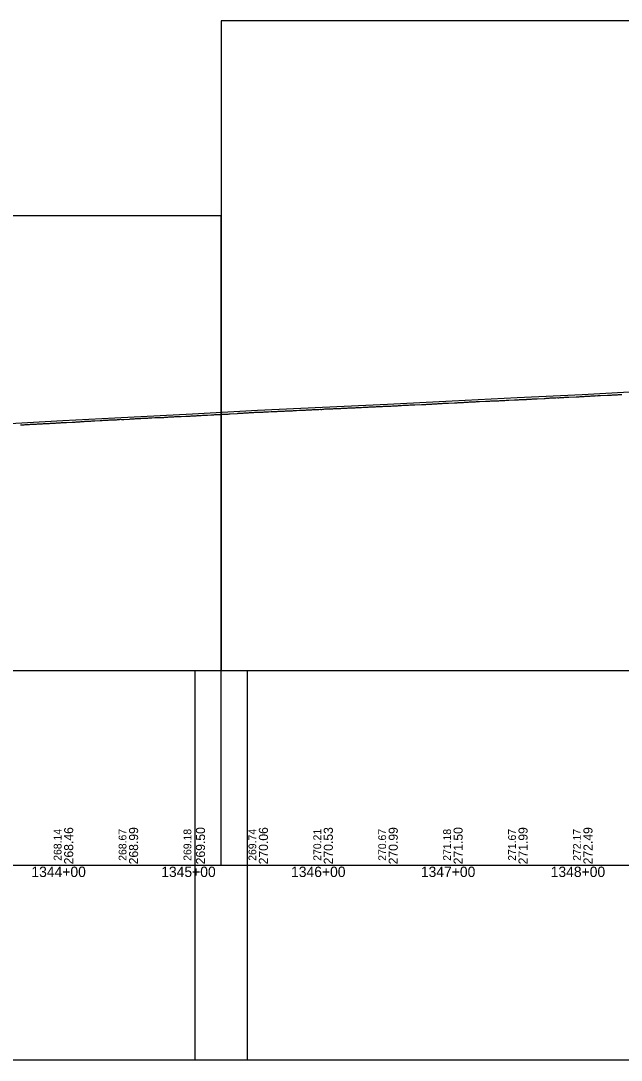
# Model space of a CAD drawing. Extents: x 2898 to 49495, y -15038 to -13538.
# Drawn here: x 23821 to 24283, y -15038 to -14238 of the extents above; entities that cross this region are included whole.
import ezdxf

# ---------------------------------------------------------------- set-up
doc = ezdxf.new("R2010")
doc.units = 0
for name, color, linetype in [('RD_DDB_Profile_EX', 7, 'Continuous'), ('RD_DDB_Profile_PR', 7, 'Continuous'), ('RD_DDB_StaTX', 7, 'Continuous'), ('RD_DDB_StripGrade', 7, 'Continuous'), ('RD_GPK_Profile_Cell', 7, 'Continuous'), ('RD_SHT_ShtClip', 7, 'Continuous')]:
    doc.layers.add(name, color=color, linetype=linetype)

msp = doc.modelspace()

# ---------------------------------------------------------------- linework, layer by layer
at = {"layer": 'RD_DDB_Profile_EX'}
for points in [[(24204.45, -14530.08), (24205.21, -14530), (24205.97, -14529.97), (24206.73, -14529.97), (24207.48, -14529.96), (24208.24, -14529.85), (24209, -14529.82), (24209.76, -14529.85), (24210.51, -14529.82), (24210.81, -14529.8), (24211.27, -14529.78), (24212.02, -14529.74), (24212.78, -14529.67), (24213.53, -14529.67), (24214.29, -14529.59), (24215.05, -14529.55), (24215.8, -14529.51), (24216.55, -14529.48), (24217.33, -14529.47), (24218.09, -14529.43), (24218.77, -14529.4), (24224.11, -14529.13), (24224.87, -14529.05), (24225.63, -14529.01), (24226.4, -14529.01), (24226.73, -14528.98), (24227.14, -14528.94), (24227.9, -14528.86), (24228.67, -14528.78), (24229.43, -14528.78), (24230.19, -14528.74), (24230.94, -14528.74), (24231.71, -14528.7), (24232.47, -14528.66), (24233.24, -14528.55), (24234, -14528.51), (24234.76, -14528.55), (24235.53, -14528.55), (24236.3, -14528.51), (24237.05, -14528.47), (24237.82, -14528.39), (24238.59, -14528.32), (24239.36, -14528.32), (24240.12, -14528.24), (24240.89, -14528.2), (24241.66, -14528.16), (24242.64, -14528.15), (24243.21, -14528.12), (24248.86, -14527.86), (24249.63, -14527.82), (24250.6, -14527.82), (24251.16, -14527.79), (24251.93, -14527.75), (24252.69, -14527.67), (24253.46, -14527.59), (24254.22, -14527.59), (24254.99, -14527.55), (24255.76, -14527.43), (24256.52, -14527.39), (24257.29, -14527.35), (24258.06, -14527.32), (24258.84, -14527.31), (24259.61, -14527.27), (24260.39, -14527.19), (24261.16, -14527.19), (24261.94, -14527.15), (24262.73, -14527.15), (24263.51, -14527.07), (24264.29, -14526.99), (24265.08, -14527.03), (24265.85, -14526.99), (24266.64, -14526.91), (24267.43, -14526.91), (24272.88, -14526.65), (24273.65, -14526.65), (24274.47, -14526.61), (24275.24, -14526.53), (24276.04, -14526.5), (24276.81, -14526.46), (24277.59, -14526.42), (24278.38, -14526.38), (24279.16, -14526.34), (24279.94, -14526.3), (24280.73, -14526.27), (24281.51, -14526.19), (24282.43, -14526.15), (24283.18, -14526.11), (24283.96, -14526.03)], [(24020.06, -14538.99), (24020.85, -14538.95), (24021.64, -14538.91), (24022.43, -14538.87), (24023.22, -14538.83), (24024.01, -14538.83), (24024.79, -14538.79), (24025.57, -14538.71), (24026.36, -14538.64), (24027.14, -14538.64), (24027.93, -14538.6), (24028.71, -14538.56), (24029.48, -14538.56), (24030.27, -14538.56), (24031.05, -14538.4), (24031.83, -14538.36), (24032.61, -14538.32), (24033.4, -14538.36), (24035.74, -14538.25), (24038.78, -14538.1), (24039.59, -14538.1), (24040.36, -14538.03), (24041.15, -14537.95), (24041.93, -14537.91), (24042.72, -14537.87), (24043.7, -14537.84), (24044.29, -14537.87), (24045.08, -14537.83), (24045.86, -14537.71), (24046.65, -14537.67), (24047.44, -14537.63), (24048.22, -14537.59), (24049, -14537.56), (24049.79, -14537.55), (24050.58, -14537.52), (24051.66, -14537.48), (24052.14, -14537.56), (24052.93, -14537.56), (24053.72, -14537.32), (24054.49, -14537.28), (24055.28, -14537.2), (24056.05, -14537.2), (24056.84, -14537.2), (24059.61, -14537.09), (24061.34, -14537.02), (24062.11, -14536.98), (24062.9, -14536.94), (24063.69, -14536.9), (24064.48, -14536.9), (24065.25, -14536.87), (24066.04, -14536.79), (24066.82, -14536.79), (24067.61, -14536.75), (24068.38, -14536.71), (24069.17, -14536.67), (24069.96, -14536.59), (24070.73, -14536.55), (24071.52, -14536.51), (24072.31, -14536.51), (24073.09, -14536.43), (24073.87, -14536.39), (24074.65, -14536.36), (24075.53, -14536.35), (24076.23, -14536.32), (24077.01, -14536.32), (24077.81, -14536.24), (24078.58, -14536.24), (24079.38, -14536.16), (24083.49, -14535.99), (24084.72, -14535.94), (24085.49, -14535.9), (24086.28, -14535.9), (24087.07, -14535.86), (24087.86, -14535.78), (24088.65, -14535.74), (24089.44, -14535.7), (24090.23, -14535.62), (24091.02, -14535.62), (24091.45, -14535.58), (24091.81, -14535.55), (24092.6, -14535.55), (24093.38, -14535.55), (24094.17, -14535.47), (24094.95, -14535.43), (24095.75, -14535.39), (24096.53, -14535.43), (24097.31, -14535.35), (24098.1, -14535.27), (24098.89, -14535.27), (24099.68, -14535.23), (24100.46, -14535.19), (24101.26, -14535.19), (24102.04, -14535.15), (24106.36, -14535), (24107.36, -14534.89), (24107.94, -14534.89), (24108.72, -14534.89), (24109.51, -14534.85), (24110.29, -14534.77), (24111.08, -14534.69), (24111.87, -14534.65)], [(24111.87, -14534.65), (24112.66, -14534.57), (24113.44, -14534.57), (24114.23, -14534.53), (24115.32, -14534.42), (24115.81, -14534.37), (24116.6, -14534.33), (24117.39, -14534.29), (24118.19, -14534.29), (24118.98, -14534.29), (24119.77, -14534.21), (24120.56, -14534.09), (24121.37, -14534.09), (24122.16, -14534.01), (24122.95, -14534.01), (24123.28, -14534.01), (24123.75, -14534.01), (24124.53, -14533.97), (24129.7, -14533.79), (24130.5, -14533.75), (24131.29, -14533.75), (24132.1, -14533.71), (24132.88, -14533.67), (24133.67, -14533.59), (24134.47, -14533.56), (24135.27, -14533.56), (24136.06, -14533.48), (24136.85, -14533.52), (24137.65, -14533.44), (24138.44, -14533.36), (24139.23, -14533.36), (24140.08, -14533.32), (24140.88, -14533.24), (24141.67, -14533.16), (24142.46, -14533.12), (24143.25, -14533.08), (24144.04, -14533.04), (24144.84, -14533), (24145.63, -14532.96), (24146.43, -14532.88), (24147.2, -14532.84), (24148, -14532.8), (24148.8, -14532.76), (24149.6, -14532.72), (24150.4, -14532.68), (24155.11, -14532.47), (24155.64, -14532.45), (24156.45, -14532.41), (24157.22, -14532.41), (24158, -14532.25), (24158.78, -14532.25), (24159.57, -14532.25), (24160.36, -14532.21), (24161.14, -14532.17), (24161.93, -14532.13), (24162.72, -14532.09), (24163.06, -14532.07), (24163.5, -14532.05), (24164.29, -14532.09), (24165.08, -14532.09), (24165.87, -14531.98), (24166.65, -14531.82), (24167.43, -14531.78), (24168.21, -14531.79), (24168.99, -14531.75), (24169.76, -14531.71), (24170.54, -14531.71), (24171.31, -14531.68), (24172.07, -14531.6), (24172.84, -14531.57), (24173.63, -14531.57), (24174.4, -14531.53), (24178.98, -14531.32), (24180.03, -14531.27), (24180.82, -14531.23), (24181.6, -14531.24), (24182.38, -14531.16), (24183.16, -14531.09), (24183.92, -14531.05), (24184.7, -14531.05), (24185.48, -14531.05), (24186.25, -14530.98), (24187.02, -14530.94), (24187.78, -14530.94), (24188.54, -14530.9), (24189.31, -14530.86), (24190.08, -14530.83), (24190.84, -14530.75), (24191.59, -14530.75), (24192.36, -14530.75), (24193.12, -14530.64), (24193.88, -14530.6), (24194.89, -14530.57), (24195.4, -14530.57), (24196.15, -14530.53), (24196.91, -14530.49), (24201.41, -14530.27), (24202.18, -14530.23), (24202.94, -14530.12), (24203.69, -14530.08), (24204.45, -14530.08)], [(23837.76, -14548.6), (23838.53, -14548.49), (23841.6, -14548.32), (23842.37, -14548.4), (23843.14, -14548.4), (23843.92, -14548.21), (23844.76, -14548.2), (23845.46, -14548.17), (23846.23, -14548.13), (23847, -14548.17), (23847.76, -14548.09), (23848.53, -14547.97), (23849.3, -14547.9), (23850.07, -14547.94), (23850.85, -14547.97), (23851.61, -14547.82), (23852.38, -14547.74), (23852.72, -14547.74), (23853.15, -14547.74), (23853.92, -14547.74), (23854.7, -14547.74), (23855.45, -14547.71), (23856.23, -14547.63), (23860.67, -14547.38), (23862.11, -14547.31), (23862.87, -14547.27), (23863.62, -14547.23), (23864.37, -14547.15), (23865.14, -14547.15), (23865.89, -14547.08), (23866.66, -14547.04), (23867.42, -14546.92), (23868.18, -14546.96), (23868.63, -14546.99), (23868.94, -14547), (23869.7, -14546.96), (23870.46, -14546.73), (23871.22, -14546.73), (23871.99, -14546.66), (23872.76, -14546.62), (23873.52, -14546.66), (23874.29, -14546.62), (23875.06, -14546.5), (23875.83, -14546.46), (23876.6, -14546.46), (23877.38, -14546.38), (23878.14, -14546.31), (23882.27, -14546.08), (23883.02, -14546.04), (23883.78, -14546.04), (23884.55, -14545.96), (23885.3, -14545.92), (23886.06, -14545.92), (23886.83, -14545.92), (23887.6, -14545.92), (23888.37, -14545.81), (23889.14, -14545.69), (23889.92, -14545.61), (23890.69, -14545.61), (23891.46, -14545.61), (23892.5, -14545.53), (23893.03, -14545.53), (23893.81, -14545.53), (23894.6, -14545.49), (23895.37, -14545.45), (23896.17, -14545.37), (23896.96, -14545.26), (23897.76, -14545.18), (23898.56, -14545.29), (23899.34, -14545.33), (23900.46, -14545.27), (23904.74, -14545.03), (23905.52, -14544.83), (23906.29, -14544.79), (23907.09, -14544.79), (23907.88, -14544.83), (23908.67, -14544.75), (23909.44, -14544.68), (23910.23, -14544.6), (23911.02, -14544.6), (23911.79, -14544.56), (23912.58, -14544.56), (23913.36, -14544.56), (23914.14, -14544.4), (23914.91, -14544.36), (23915.69, -14544.33), (23916.47, -14544.25), (23917.25, -14544.25), (23918.02, -14544.29), (23918.8, -14544.29), (23919.57, -14544.17), (23920.35, -14544.17), (23921.13, -14544.09), (23921.9, -14544.02), (23924.33, -14543.91), (23926.5, -14543.82), (23927.28, -14543.9), (23928.05, -14543.86), (23928.83, -14543.74), (23929.61, -14543.7), (23930.4, -14543.7)], [(23930.4, -14543.7), (23931.17, -14543.7), (23931.95, -14543.55), (23932.29, -14543.53), (23932.73, -14543.51), (23933.51, -14543.47), (23934.28, -14543.47), (23935.06, -14543.35), (23935.84, -14543.39), (23936.62, -14543.39), (23937.4, -14543.35), (23938.18, -14543.31), (23938.96, -14543.16), (23939.74, -14543.12), (23940.52, -14543.12), (23941.3, -14543.04), (23942.08, -14543.04), (23942.87, -14543.04), (23943.65, -14543), (23944.44, -14542.92), (23948.21, -14542.76), (23949.83, -14542.69), (23950.63, -14542.69), (23951.41, -14542.65), (23952.2, -14542.57), (23952.99, -14542.61), (23953.78, -14542.49), (23954.56, -14542.45), (23955.35, -14542.41), (23956.17, -14542.41), (23956.92, -14542.37), (23957.71, -14542.33), (23958.49, -14542.29), (23959.28, -14542.26), (23960.06, -14542.18), (23960.85, -14542.1), (23961.63, -14542.06), (23962.41, -14542.02), (23963.2, -14542.02), (23964.12, -14541.97), (23964.76, -14541.94), (23967.43, -14541.78), (23968.21, -14541.74), (23969, -14541.7), (23969.78, -14541.66), (23970.57, -14541.59), (23971.35, -14541.59), (23972.13, -14541.55), (23972.92, -14541.47), (23973.7, -14541.51), (23974.49, -14541.47), (23975.28, -14541.47), (23976.06, -14541.35), (23976.85, -14541.31), (23977.64, -14541.27), (23978.42, -14541.15), (23979.21, -14541.11), (23980.04, -14541.11), (23980.79, -14541.11), (23981.57, -14541.03), (23982.37, -14540.99), (23987.65, -14540.67), (23988, -14540.64), (23988.44, -14540.59), (23989.25, -14540.59), (23990.03, -14540.48), (23990.82, -14540.44), (23991.61, -14540.48), (23992.41, -14540.4), (23993.19, -14540.32), (23993.98, -14540.2), (23994.76, -14540.16), (23995.56, -14540.16), (23995.95, -14540.14), (23996.34, -14540.12), (23997.13, -14540.04), (23997.91, -14540), (23998.21, -14539.99), (23999.01, -14539.99), (23999.79, -14539.91), (24000.58, -14539.83), (24001.37, -14539.75), (24002.16, -14539.75), (24002.94, -14539.79), (24003.91, -14539.74), (24004.52, -14539.71), (24005.31, -14539.63), (24006.09, -14539.6), (24006.9, -14539.59), (24007.68, -14539.59), (24008.46, -14539.56), (24011.87, -14539.39), (24013.77, -14539.3), (24014.55, -14539.3), (24015.33, -14539.26), (24016.11, -14539.22), (24016.91, -14539.18), (24017.69, -14539.14), (24018.47, -14539.11), (24019.27, -14539.03), (24020.06, -14538.99)], [(23820.88, -14549.45), (23822.95, -14549.34), (23823.73, -14549.34), (23824.5, -14549.27), (23825.29, -14549.23), (23826.07, -14549.19), (23826.85, -14549.11), (23827.63, -14549.07), (23828.4, -14549.03), (23828.84, -14548.99), (23829.19, -14548.95), (23829.97, -14548.95), (23830.75, -14548.91), (23831.53, -14548.88), (23832.32, -14548.88), (23833.09, -14548.88), (23833.87, -14548.76), (23834.65, -14548.72), (23835.43, -14548.64), (23836.21, -14548.6), (23836.98, -14548.6), (23837.76, -14548.6)]]:
    msp.add_lwpolyline(points, dxfattribs=at)
at = {"layer": 'RD_DDB_Profile_PR'}
msp.add_lwpolyline([(23353.38, -14570.82), (23403.38, -14568.35), (23453.38, -14565.89), (23503.38, -14563.12), (23553.38, -14560.59), (23603.38, -14558.11), (23653.38, -14555.72), (23703.38, -14553.28), (23753.38, -14550.91), (23803.38, -14548.81), (23853.38, -14546.14), (23903.38, -14543.5), (23953.38, -14540.95), (24003.38, -14538.17), (24053.38, -14535.82), (24103.38, -14533.51), (24153.38, -14530.95), (24203.38, -14528.49), (24253.38, -14526), (24303.38, -14523.38)], dxfattribs=at)
at = {"layer": 'RD_GPK_Profile_Cell'}
msp.add_line((2976.05, -14888.47), (48721.13, -14888.47), dxfattribs=at)
at = {"layer": 'RD_SHT_ShtClip'}
for points in [[(23975.38, -14238.47), (23975.38, -14738.47), (25475.38, -14738.47), (25475.38, -14738.47), (25475.38, -14238.47), (25475.38, -14238.47)], [(22475.38, -14388.47), (22475.38, -14888.47), (23975.38, -14888.47), (23975.38, -14888.47), (23975.38, -14388.47), (23975.38, -14388.47)], [(22455.38, -14738.47), (23995.38, -14738.47), (23995.38, -15038.47), (22455.38, -15038.47)], [(23955.38, -14738.47), (25495.38, -14738.47), (25495.38, -15038.47), (23955.38, -15038.47)]]:
    msp.add_lwpolyline(points, close=True, dxfattribs=at)

# ---------------------------------------------------------------- texts
at = {"layer": 'RD_DDB_StaTX'}
for s, p in [('1344+00', (23829.18, -14897.47)), ('1345+00', (23929.18, -14897.47)), ('1346+00', (24029.18, -14897.47)), ('1347+00', (24129.18, -14897.47)), ('1348+00', (24229.18, -14897.47))]:
    msp.add_text(s, height=8, dxfattribs=at).set_placement(p)
at = {"layer": 'RD_DDB_StripGrade'}
for s, height, p in [('268.14', 6, (23852.38, -14884.98)), ('268.46', 7, (23861.38, -14887.72)), ('268.67', 6, (23902.38, -14884.98)), ('268.99', 7, (23911.38, -14887.72)), ('269.18', 6, (23952.38, -14884.98)), ('269.50', 7, (23962.92, -14887.72)), ('269.74', 6, (24002.38, -14884.98)), ('270.06', 7, (24011.38, -14887.72)), ('270.21', 6, (24052.38, -14884.98)), ('270.53', 7, (24061.38, -14887.72)), ('270.67', 6, (24102.38, -14884.98)), ('270.99', 7, (24111.38, -14887.72)), ('271.18', 6, (24152.38, -14884.98)), ('271.50', 7, (24161.38, -14887.72)), ('271.67', 6, (24202.38, -14884.98)), ('271.99', 7, (24211.38, -14887.72)), ('272.17', 6, (24252.38, -14884.98)), ('272.49', 7, (24261.38, -14887.72))]:
    msp.add_text(s, height=height, rotation=90, dxfattribs=at).set_placement(p)

doc.saveas('drawing.dxf')
